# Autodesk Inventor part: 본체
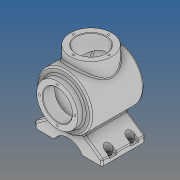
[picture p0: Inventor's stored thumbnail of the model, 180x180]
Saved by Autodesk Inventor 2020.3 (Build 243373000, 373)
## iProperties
Created: 2021-04
Part Number: 본체
Material: 알루미늄 6061
Document SubType Name: Modeling
Designer: EZDESIGN
Density: 2.7 g/cm^3
Appearance: 기본값
Mass: 1642.25 g
Surface Area: 1046.13 cm^2
Volume: 608.24 cm^3
Author: EZDESIGN
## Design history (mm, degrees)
sketch "스케치1"
  geometry: L1 (0, 60)-(0, -60); L2 (27, 60)-(38, 60); L3 (38, 60)-(38, 48); L4 (38, 48)-(50, 48); L5 (50, 48)-(50, -37.05); L6 (50, -60)-(27, -60); L7 (27, 60)-(27, 38); L8 (27, 38)-(37, 38); L9 (40, 35)-(40, -39.903); L10 (40, -52.683)-(40, -52.948); L11 (40, -41.916)-(40, -52.683); L12 (50, -48.336)-(50, -60); L13 (50, -37.05)-(50, -48.336); A1 r 113 centre (0, 53) between (-82.658, -24.049) and (0, -60); A2 r 103 centre (0, 53) between (-75.343, -17.231) and (0, -50); A3 r 103 centre (0, 53) between (40, -41.916) and (50, -37.05); A4 r 103 centre (0, 53) between (0, -50) and (38.11, -42.69); A5 r 113 centre (0, 53) between (0, -60) and (50, -48.336); A6 r 3 centre (37, -39.903) between (38.11, -42.69) and (40, -39.903); A7 r 3 centre (37, 35) between (40, 35) and (37, 38); 2 further points
  constraints: 26 end point, 17 point on circle, 12 perpendicular, 7 centre point, 6 tangent, 3 point on line, 2 horizontal alignment, 2 vertical, 1 coincident, 1 equal radius, 1 horizontal, 1 midpoint
  dimensions: "d0" = 12 distance between parallel lines of L4 L2; "d1" = 108 distance of L4.end L6.start; "d2" = 100 diameter of L5 L1; "d3" = 76 diameter of L3 L1; "d4" = 54 diameter of L7 L1; "d5" = 80 diameter of L9 L1; "d6" = 22 distance of L2.start L7.end; "d7" = 113 radius of A1; "d8" = 10 radial gap between concentric circles of A1 A2; "d9" = 3 radius of A6
revolve "회전1" sketch "스케치1" stored, may be unused: angle "d10" = 90 deg
chamfer "모따기1" distance "d11" = 1; stored, may be unused: second distance "d12" = 2, angle "d13" = 45 deg
node "작업 평면1"
sketch "스케치4"
  geometry: A1 r 32.5 centre (0, 0) between (0, 32.5) and (0, -32.5); 3 further points
  constraints: 4 point on circle, 2 horizontal alignment, 2 vertical alignment, 1 centre point, 1 coincident
  dimensions: "d24" = 65 diameter of A1
hole "구멍1" sketch "스케치4" at (0, 32.5), (0, -32.5), (32.5, 0), (-32.5, 0) diameter "d25" = 3.45873; stored, may be unused: countersink angle "d29" = 90 deg, drill point angle "d31" = 118 deg; dims "d26" = 8, "d27" = 4, "d28" = 2, "d30" = 10
sketch "스케치7"
  geometry: L1 (-9.425, -30.186)-(-17.608, -35.916); L2 (-62, -67)-(-62, -77); L3 (-62, -77)-(62, -77); L4 (62, -77)-(62, -67); L5 (62, -67)-(17.608, -35.916); L6 (-9.425, -30.186)-(9.425, -30.186); L7 (0, 0)-(0, -81.277); L8 (17.608, -35.916)-(9.425, -30.186); L9 (-17.608, -35.916)-(-62, -67); L10 (-62, -62)-(88.458, -62); C1 r 50 at (0, 0) reference; A1 r 30 centre (0, -92) between (27.485, -104.024) and (-29.766, -88.263); A2 r 40 centre (0, 0) between (17.608, -35.916) and (-17.608, -35.916) reference; 6 further points
  constraints: 20 end point, 4 point on circle, 2 horizontal, 2 midpoint, 2 perpendicular, 2 vertical, 2 vertical alignment, 1 centre point, 1 collinear, 1 point on line, 1 tangent
  dimensions: "d44" = 30 radius of A1; "d45" = 10 distance of L2.start L2.end; "d46" = 10 distance of L3.end L4.end; "d47" = 77 distance from line of L3 L7.start; "d48" = 55 deg angle of L2 L1; "d49" = 55 deg angle of L4 L5; "d50" = 124 distance of L2.end L3.end; "d51" = 15 distance between parallel lines of L3 L10
extrude "돌출3" join sketch "스케치7" stored distance "d52" = 80; taper "d53" = 0 deg
node "작업 평면3"
sketch "스케치10"
  geometry: L1 (36.019, -80)-(36.019, 0) reference; L2 (-87.981, -80)-(-87.981, 0) reference; L3 (0.713, -80)-(36.019, -80) reference; 5 further points
  constraints: 2 horizontal alignment, 2 vertical alignment
  dimensions: "d56" = 8 distance from line of point (28.019, -60) L1; "d57" = 8 distance from line of L2 point (-79.981, -60); "d58" = 108 distance of point (28.019, -60) point (-79.981, -60) (derived); "d59" = 20 distance from line of point (28.019, -60) L3; "d60" = 40 distance of point (28.019, -20) point (28.019, -60)
hole "구멍3" sketch "스케치10" diameter "d61" = 9; stored, may be unused: countersink angle "d65" = 90 deg, drill point angle "d67" = 118 deg; dims "d62" = 8, "d63" = 14, "d64" = 20, "d66" = 26
node "작업 평면4"
sketch "스케치13"
  geometry: L1 (-63.981, 20)-(12.019, 20) reference; C1 r 38 at (-25.981, -42); 1 further point
  constraints: 1 centre point, 1 vertical alignment
  dimensions: "d70" = 76 diameter of C1; "d71" = 62 distance from line of L1 C1.centre
extrude "돌출4" join sketch "스케치13" stored distance "d72" = 10; taper "d73" = 0 deg
sketch "스케치14"
  geometry: L1 (38, -62)-(-38, -62) reference; C1 r 38 at (0, 0) reference; C2 r 27 at (0, 0); 1 further point
  constraints: 1 centre point, 1 coincident
  dimensions: "d75" = 54 diameter of C2
extrude "돌출5" cut sketch "스케치14" stored distance "d76" = 10; taper "d77" = 0 deg; dims "d0" = 12, "d1" = 108, "d2" = 100, "d3" = 76, "d4" = 54, "d5" = 80, "d6" = 22, "d7" = 113, "d8" = 10, "d9" = 3
sketch "스케치15"
  geometry: C1 r 27 at (0, 0) reference; C2 r 38 at (0, 0) reference; A1 r 32.5 centre (0, 0) between (-32.5, 0) and (0, -32.5); 3 further points
  constraints: 4 point on circle, 2 horizontal alignment, 2 vertical alignment, 1 centre point, 1 concentric
  dimensions: "d78" = 65 diameter of A1
hole "구멍4" sketch "스케치15" at (-32.5, 0), (0, -32.5), (0, 32.5), (32.5, 0) diameter "d79" = 3.45873; stored, may be unused: countersink angle "d83" = 90 deg, drill point angle "d85" = 118 deg; dims "d80" = 8, "d81" = 14, "d82" = 20, "d84" = 10
chamfer "모따기3" distance "d86" = 1; stored, may be unused: second distance "d87" = 2, angle "d88" = 45 deg
fillet "모깎기1" dims "d89" = 3
sketch "스케치16"
  geometry: L1 (8, 17)-(8, -57) reference; L2 (5, -60)-(-32.576, -60) reference; L3 (-32.576, -60)-(-32.576, 20) reference; L4 (-32.576, 20)-(5, 20) reference; L5 (-113, 20)-(-75.424, 20) reference; L6 (-75.424, 20)-(-75.424, -60) reference; L7 (-75.424, -60)-(-113, -60) reference; L8 (-116, -57)-(-116, 17) reference; L9 (0, 7)-(8, 7); L10 (0, -7)-(8, -7); L11 (0, -33)-(8, -33); L12 (0, -47)-(8, -47); L13 (-108, -47)-(-116, -47); L14 (-108, -33)-(-116, -33); L15 (-108, -7)-(-116, -7); L16 (-108, 7)-(-116, 7); C1 r 4.5 at (0, -40) reference; C2 r 4.5 at (-108, 0) reference; C3 r 4.5 at (-108, -40) reference; C4 r 4.5 at (0, 0) reference; A1 r 3 centre (5, 17) between (8, 17) and (5, 20) reference; A2 r 3 centre (5, -57) between (5, -60) and (8, -57) reference; A3 r 3 centre (-113, -57) between (-116, -57) and (-113, -60) reference; A4 r 3 centre (-113, 17) between (-113, 20) and (-116, 17) reference; A5 r 7 centre (0, -40) between (0, -33) and (0, -47) reference; A6 r 7 centre (-108, 0) between (-108, -7) and (-108, 7) reference; A7 r 7 centre (-108, -40) between (-108, -47) and (-108, -33) reference; A8 r 7 centre (0, 0) between (0, 7) and (0, -7) reference; 1 further point
  constraints: 16 end point, 16 point on line, 8 point on circle, 4 tangent, 3 perpendicular, 1 parallel
extrude "돌출6" cut sketch "스케치16" distance "d90" = 14; taper "d91" = 0 deg
fillet "모깎기2" dims "d92" = 3
fillet "모깎기3" dims "d93" = 3
node "작업 평면10"
sketch "스케치22"
  geometry: L1 (-41.242, 43.086)-(41.242, 43.086); L2 (41.242, 43.086)-(41.242, -43.086); L3 (41.242, -43.086)-(-41.242, -43.086); L4 (-41.242, -43.086)-(-41.242, 43.086); L5 (-41.242, 0)-(41.242, 0); L6 (0, 43.086)-(0, -43.086); 2 further points
  constraints: 5 midpoint, 4 end point, 1 coincident, 2 other
  dimensions: "d97" = 86.17112 distance of L6.start L6.end; "d98" = 82.48327 distance of L5.start L5.end
extrude "돌출7" join sketch "스케치22" stored distance "d100" = 10; taper "d101" = 0 deg
node "솔리드1"
node "절단 모서리 투영1"
node "절단 모서리 투영3"
node "절단 모서리 투영4"
node "절단 모서리 투영5"
feature "A9D066F2-1C7D-4E18-AEED-F7BC21143FA4" dims "d61" = 9, "d62" = 8, "d63" = 14, "d64" = 20, "d65" = 90 deg, "d66" = 26, "d67" = 118 deg
other parameters: "d14" = 65, "d55" = -26, "d69" = -142
